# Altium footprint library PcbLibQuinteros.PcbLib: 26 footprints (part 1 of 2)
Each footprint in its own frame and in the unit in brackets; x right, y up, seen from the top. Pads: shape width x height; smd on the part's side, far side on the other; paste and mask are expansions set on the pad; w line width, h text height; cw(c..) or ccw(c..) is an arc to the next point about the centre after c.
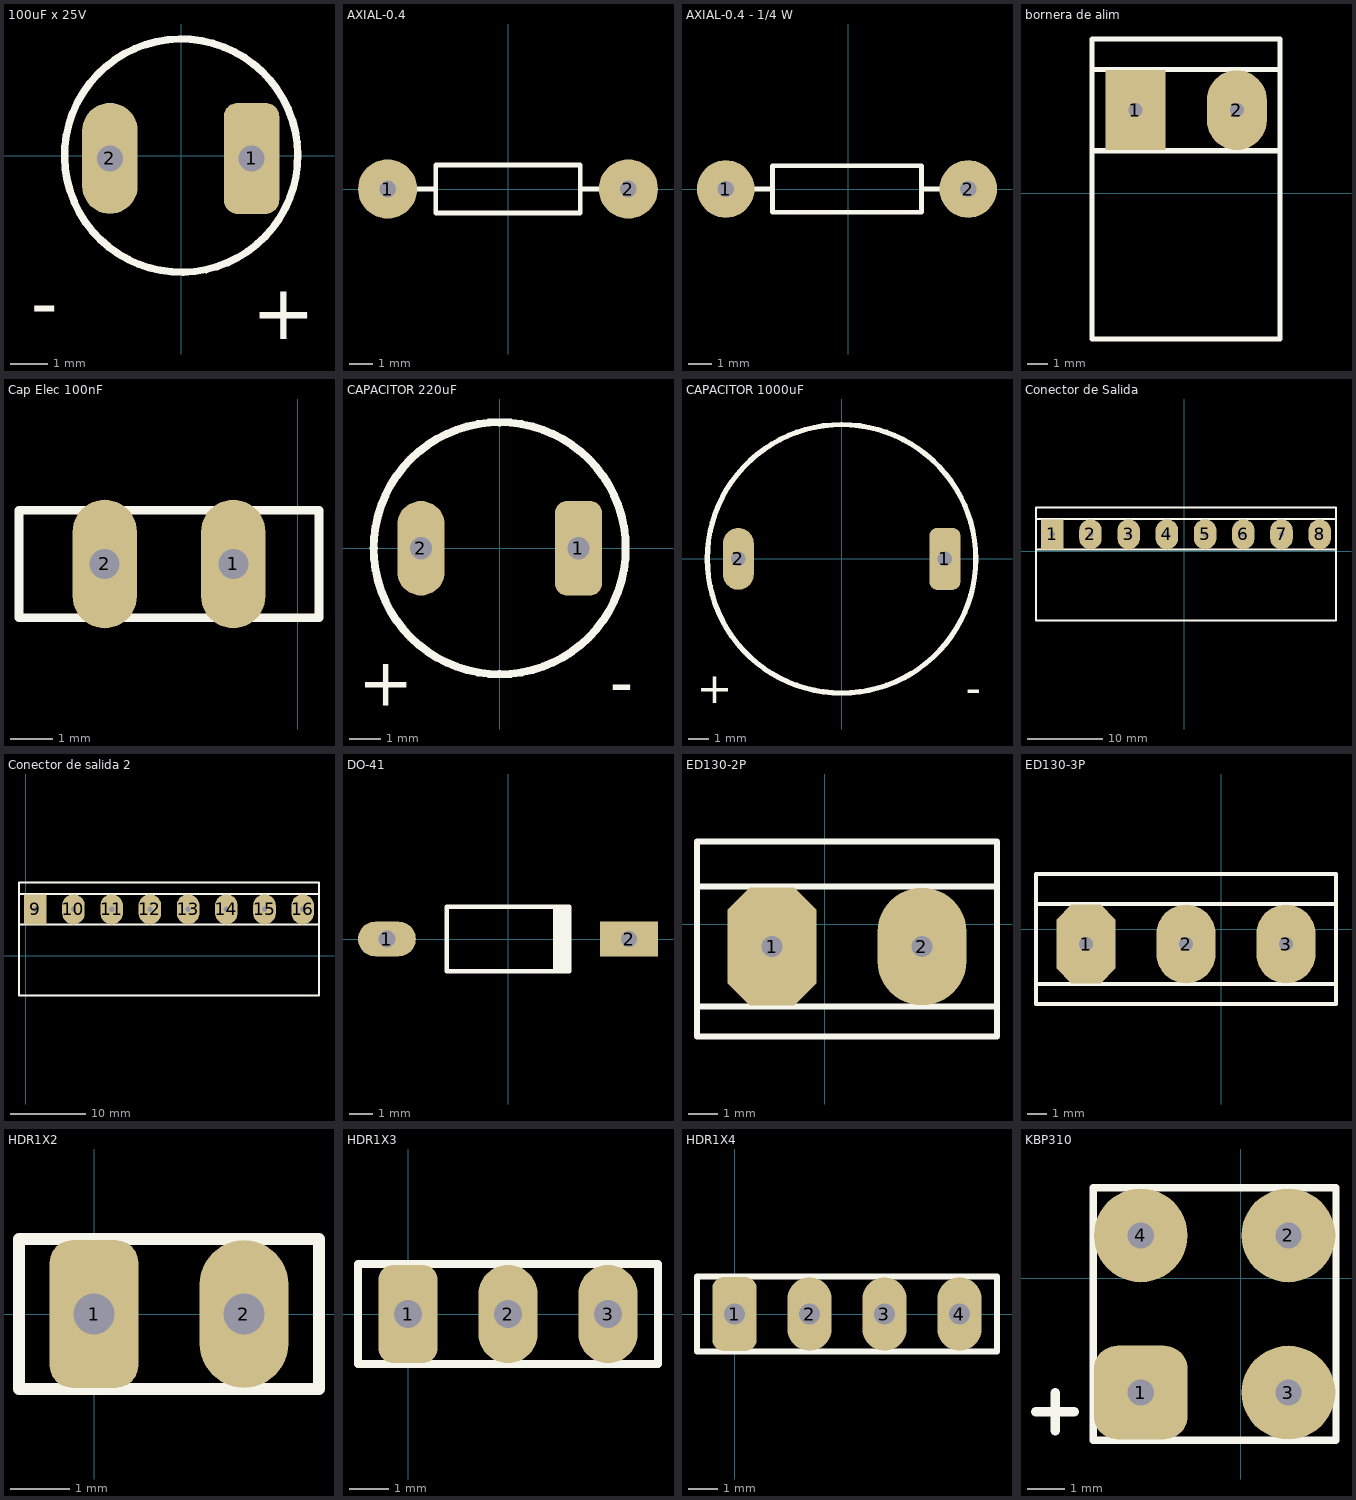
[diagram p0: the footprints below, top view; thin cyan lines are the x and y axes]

## 100uF x 25V [mm] "Polarized Capacitor; 2 Leads"
height 5.08
pads (2):
  rrect50% 1.5x3 hole 0.7: 1(1.9,-0.075)
  oval 1.5x3 hole 0.7: 2(-1.925,-0.075)
Top Overlay:
  lines w0.2: 2.996,0.972 ccw(c0,0) 2.998,0.966
  text "-" at -4.064,-4.699 h1.5
  text "+" at 1.905,-4.953 h1.5

## AXIAL-0.4 [mm] "Axial Device, Thru-Hole; 2 Leads; 0.4 in Pin Spacing"
height 2.032
pads (2):
  round 2.5 hole 0.7: 1(-5.08,0) 2(5.08,0)
Top Overlay:
  lines w0.2: -4.064,0 -3.048,0 ; 3.048,0 4.064,0 ; -3.048,-1.016 -3.048,1.016 3.048,1.016 3.048,-1.016 -3.048,-1.016

## AXIAL-0.4 - 1/4 W [mm] "Axial Device, Thru-Hole; 2 Leads; 0.4 in Pin Spacing"
height 2.032
pads (2):
  round 2.5 hole 0.7: 1(-5.334,0) 2(5.207,0)
Top Overlay:
  lines w0.2: -4.064,0 -3.302,0 ; 3.175,0 3.937,0 ; -3.302,-1.016 3.175,-1.016 3.175,1.016 -3.302,1.016 -3.302,-1.016

## bornera de alim [mm]
pads (2):
  rect 3x4 hole 0.7: 1(-14.2,4.159)
  oval 3x4 hole 0.7: 2(-9.12,4.159)
Top Overlay:
  lines w0.254: -16.359,6.198 -6.968,6.198 ; -16.358,2.127 -6.968,2.127 ; -6.968,-7.285 -16.359,-7.285 -16.359,7.715 -6.968,7.715 ; -6.968,-7.267 -6.968,4.159 -6.968,7.698

## Cap Elec 100nF [mm] "Polarized Capacitor (Radial); 2 Leads"
pads (2):
  oval 1.5x3 hole 0.7: 1(-1.5,4.25) 2(-4.5,4.25)
Top Overlay:
  lines w0.2: -6.5,3 -6.5,5.5 0.5,5.5 0.5,3 -6.5,3

## CAPACITOR 220uF [mm]
pads (2):
  rrect50% 1.5x3 hole 0.7: 1(2.5,0)
  oval 1.5x3 hole 0.7: 2(-2.5,0)
Top Overlay:
  circle w0.254: c0,0 r4
  text "+" at -4.5,-5 h1.52
  text "-" at 3.5,-5 h1.52

## CAPACITOR 1000uF [mm]
pads (2):
  rrect50% 1.5x3 hole 0.7: 1(5,0)
  oval 1.5x3 hole 0.7: 2(-5,0)
Top Overlay:
  circle w0.254: c0,0 r6.5
  text "-" at 6,-7 h1.52
  text "+" at -7,-7 h1.52

## Conector de Salida [mm]
pads (8):
  rect 3x4 hole 0.7: 1(-17.579,2.229)
  oval 3x4 hole 0.7: 2(-12.499,2.229) 3(-7.419,2.229) 4(-2.339,2.229) 5(2.741,2.229) 6(7.821,2.229) 7(12.901,2.229) 8(17.981,2.229)
Top Overlay:
  lines w0.254: -19.738,4.267 20.14,4.267 ; -19.736,0.197 20.142,0.197 ; -19.738,-9.215 20.14,-9.215 20.14,5.785 -19.738,5.785 -19.738,-9.215

## Conector de salida 2 [mm]
pads (8):
  rect 3x4 hole 0.7: 9(1.268,6.191)
  oval 3x4 hole 0.7: 10(6.348,6.191) 11(11.428,6.191) 12(16.508,6.191) 13(21.588,6.191) 14(26.668,6.191) 15(31.748,6.191) 16(36.828,6.191)
Top Overlay:
  lines w0.254: -0.891,8.23 38.987,8.23 ; -0.889,4.159 38.989,4.159 ; -0.891,-5.253 -0.891,9.747 38.987,9.747 38.987,-5.253 -0.891,-5.253

## DO-41 [mm] "Diode, Axial; Body 5.2 x 2.7 mm (LxDia. max), Lead Dia. 0.86 mm (max)"
height 2.8
pads (2):
  oval 2.5x1.5 hole 0.74: 1(-5.23,0)
  rect 2.5x1.5 hole 0.7: 2(5.23,0)
Top Overlay:
  rectangle: 1.95,-1.4 2.75,1.4
  lines w0.2: 2.65,-1.4 -2.65,-1.4 -2.65,1.4 2.65,1.4

## ED130-2P [mm] "Connector; Header; 2 Position"
pads (2):
  oct 3x4 hole 0.7: 1(-1.778,-0.762)
  oval 3x4 hole 0.7: 2(3.302,-0.762)
Top Overlay:
  lines w0.2: -4.318,-2.794 5.842,-2.794 ; -4.318,1.27 4.572,1.27 5.842,1.27 ; -4.318,1.27 -4.318,2.794 5.842,2.794 5.842,1.27 ; -4.318,1.27 -4.318,-2.667 -4.318,-3.81 5.842,-3.81 5.842,-2.667 5.842,1.27

## ED130-3P [mm] "Connector; Header; 2 Position"
pads (3):
  oct 3x4 hole 0.7: 1(-6.858,-0.762)
  oval 3x4 hole 0.7: 2(-1.778,-0.762) 3(3.302,-0.762)
Top Overlay:
  lines w0.2: -9.398,-2.794 5.842,-2.794 ; -9.398,1.27 -9.398,-2.667 -9.398,-3.81 5.842,-3.81 5.842,-2.667 5.842,1.27 ; -9.398,1.27 -9.398,2.794 5.842,2.794 5.842,1.27 ; -9.398,1.27 4.572,1.27 5.842,1.27

## HDR1X2 [mm] "Connector; Header; 2 Position"
pads (2):
  rrect50% 1.5x2.5 hole 0.7: 1(0,0)
  oval 1.5x2.5 hole 0.7: 2(2.54,0)
Top Overlay:
  lines w0.2: -1.27,-1.27 3.81,-1.27 3.81,1.27 -1.27,1.27 -1.27,-1.27

## HDR1X3 [mm] "Connector; Header; 3 Position"
pads (3):
  rrect50% 1.5x2.5 hole 0.7: 1(0,0)
  oval 1.5x2.5 hole 0.7: 2(2.54,0) 3(5.08,0)
Top Overlay:
  lines w0.2: -1.27,-1.27 6.35,-1.27 6.35,1.27 -1.27,1.27 -1.27,-1.27

## HDR1X4 [mm] "Connector; Header; 4 Position"
pads (4):
  rrect50% 1.5x2.5 hole 0.7: 1(0,0)
  oval 1.5x2.5 hole 0.7: 2(2.54,0) 3(5.08,0) 4(7.62,0)
Top Overlay:
  lines w0.2: -1.27,-1.27 -1.27,1.27 8.89,1.27 8.89,-1.27 -1.27,-1.27

## KBP310 [mm] "Axial Device, Thru-Hole; 2 Leads; 0.4 in Pin Spacing"
height 2.032
pads (4):
  rrect50% 2.5x2.5 hole 0.7: 1(-2.667,-3.048)
  round 2.5 hole 0.7: 2(1.27,1.143) 3(1.27,-3.048) 4(-2.667,1.143)
Top Overlay:
  lines w0.2: -3.937,-4.318 -3.937,2.413 2.54,2.413 2.54,-4.318 -3.937,-4.318
  lines w0.254: -5.461,-3.556 -4.445,-3.556 ; -4.953,-4.064 -4.953,-3.048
